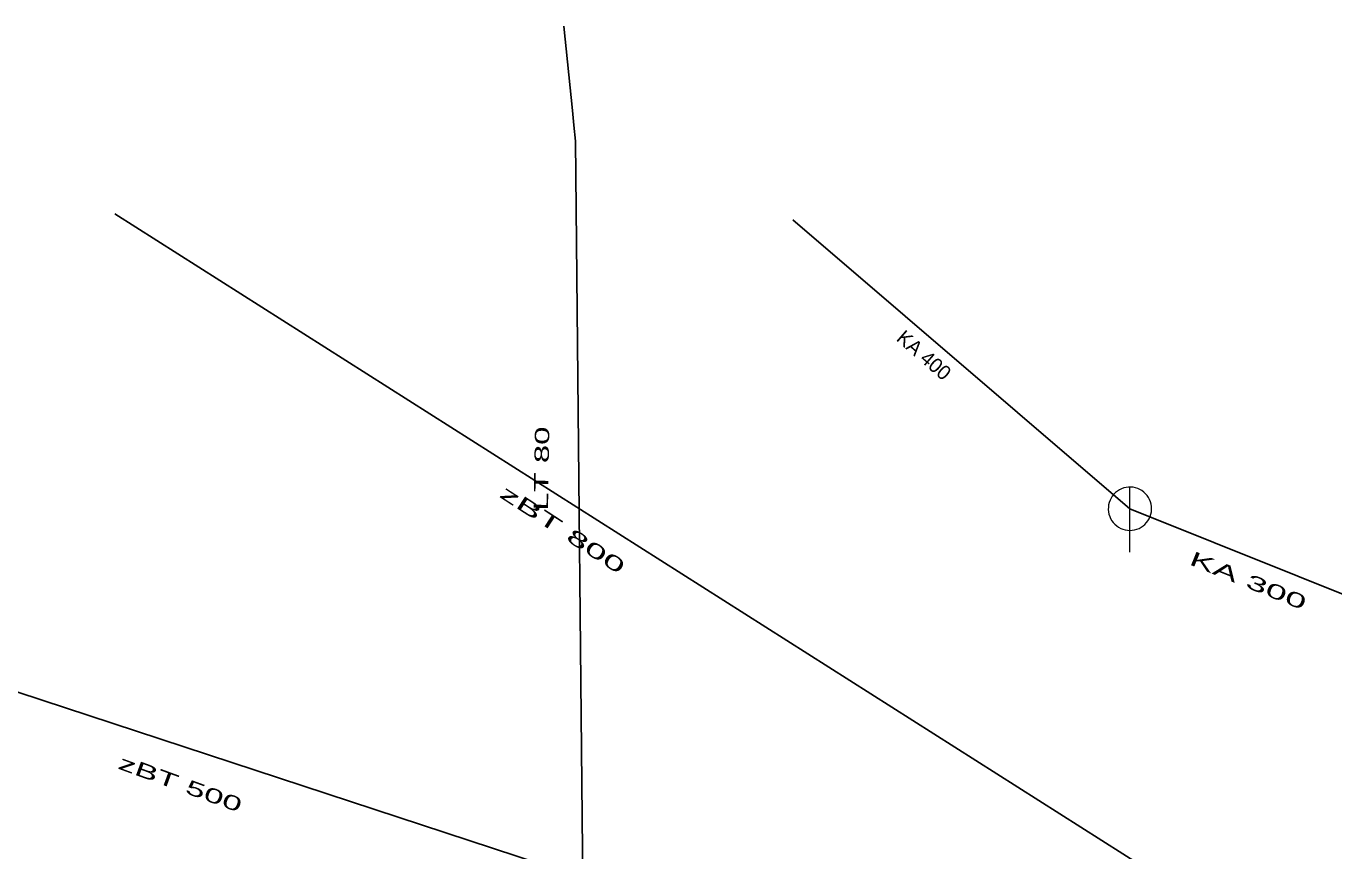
# Model space of a CAD drawing. Extents: x -688432 to -687974, y -973332 to -972704.
# Drawn here: x -688275.2 to -688214.9, y -972876 to -972837.9 of the extents above; entities that cross this region are included whole.
import ezdxf
from ezdxf.enums import TextEntityAlignment as Align

# ---------------------------------------------------------------- set-up
doc = ezdxf.new("R2010")
doc.units = 0
doc.header["$LTSCALE"] = 0.27
for name, color, linetype, lineweight in [('1', 7, 'Continuous', 25), ('14', 7, 'Continuous', 25), ('17', 7, 'Continuous', 25), ('22', 7, 'Continuous', 13)]:
    doc.layers.add(name, color=color, linetype=linetype, lineweight=lineweight)

msp = doc.modelspace()

# ---------------------------------------------------------------- linework, layer by layer
at = {"layer": '14'}
for p, q in [((-688221.777, -972877.88), (-688271.103, -972846.579)), ((-688224.272, -972860.177), (-688239.823, -972846.848))]:
    msp.add_line(p, q, dxfattribs=at)
for points in [[(-688207.188, -972867.028), (-688212.648, -972864.838), (-688224.272, -972860.177)], [(-688217.084, -972889.702), (-688227.642, -972884.745), (-688247.084, -972877.999), (-688290.938, -972863.596)]]:
    msp.add_lwpolyline(points, dxfattribs=at)
at = {"layer": '17'}
msp.add_lwpolyline([(-688249.47, -972882.184), (-688249.846, -972843.218), (-688249.92, -972842.489), (-688249.989, -972841.809), (-688250.385, -972837.918)], dxfattribs=at)
at = {"layer": '22'}
msp.add_line((-688224.272, -972862.177), (-688224.271, -972859.177), dxfattribs=at)
msp.add_lwpolyline([(-688223.272, -972860.177), (-688223.277, -972860.068), (-688223.295, -972859.96), (-688223.325, -972859.854), (-688223.365, -972859.753), (-688223.417, -972859.656), (-688223.479, -972859.566), (-688223.551, -972859.483), (-688223.631, -972859.409), (-688223.719, -972859.343), (-688223.813, -972859.288), (-688223.913, -972859.243), (-688224.018, -972859.21), (-688224.125, -972859.188), (-688224.234, -972859.178), (-688224.344, -972859.18), (-688224.452, -972859.194), (-688224.559, -972859.219), (-688224.662, -972859.256), (-688224.76, -972859.305), (-688224.852, -972859.363), (-688224.938, -972859.432), (-688225.015, -972859.509), (-688225.084, -972859.595), (-688225.143, -972859.687), (-688225.191, -972859.785), (-688225.228, -972859.888), (-688225.254, -972859.995), (-688225.268, -972860.103), (-688225.271, -972860.213), (-688225.261, -972860.322), (-688225.24, -972860.429), (-688225.206, -972860.533), (-688225.162, -972860.633), (-688225.107, -972860.728), (-688225.041, -972860.816), (-688224.967, -972860.896), (-688224.884, -972860.968), (-688224.794, -972861.03), (-688224.698, -972861.082), (-688224.596, -972861.123), (-688224.491, -972861.153), (-688224.383, -972861.171), (-688224.273, -972861.177), (-688224.164, -972861.171), (-688224.056, -972861.153), (-688223.951, -972861.124), (-688223.849, -972861.083), (-688223.752, -972861.031), (-688223.662, -972860.969), (-688223.579, -972860.898), (-688223.504, -972860.818), (-688223.439, -972860.73), (-688223.383, -972860.636), (-688223.339, -972860.536), (-688223.305, -972860.432), (-688223.283, -972860.324), (-688223.273, -972860.215)], close=True, dxfattribs=at)

# ---------------------------------------------------------------- texts
at = {"layer": '1'}
msp.add_text('KA 400', height=0.6667, rotation=319, dxfattribs=at).set_placement((-688233.9901, -972853.3445), align=Align.CENTER)
msp.add_text('KA 400', height=0.6667, rotation=319, dxfattribs=at).set_placement((-688233.9901, -972853.3445), align=Align.CENTER)
msp.add_text('KA 400', height=0.6667, rotation=319, dxfattribs=at).set_placement((-688233.9901, -972853.3445), align=Align.CENTER)
msp.add_text('KA 400', height=0.6667, rotation=319, dxfattribs=at).set_placement((-688233.9901, -972853.3445), align=Align.CENTER)
msp.add_text('KA 400', height=0.6667, rotation=319, dxfattribs=at).set_placement((-688233.9901, -972853.3445), align=Align.CENTER)
for s, rotation, width, p in [('LT 80 ', 89, 1.7, (-688251.0809, -972858.1198)), ('LT 80 ', 89, 1.7, (-688251.0809, -972858.1198)), ('LT 80 ', 89, 1.7, (-688251.0809, -972858.1198)), ('LT 80 ', 89, 1.7, (-688251.0809, -972858.1198)), ('LT 80 ', 89, 1.7, (-688251.0809, -972858.1198)), ('zBT 800 ', 327, 2, (-688250.4165, -972861.5496)), ('zBT 800 ', 327, 2, (-688250.4165, -972861.5496)), ('zBT 800 ', 327, 2, (-688250.4165, -972861.5496)), ('zBT 800 ', 327, 2, (-688250.4165, -972861.5496)), ('zBT 800 ', 327, 2, (-688250.4165, -972861.5496)), ('KA 300', 338, 1.95, (-688218.9409, -972863.7974)), ('KA 300', 338, 1.95, (-688218.9409, -972863.7974)), ('KA 300', 338, 1.95, (-688218.9409, -972863.7974)), ('KA 300', 338, 1.95, (-688218.9409, -972863.7974)), ('KA 300', 338, 1.95, (-688218.9409, -972863.7974)), ('zBT 500 ', 340, 1.8, (-688267.982, -972873.2478)), ('zBT 500 ', 340, 1.8, (-688267.982, -972873.2478)), ('zBT 500 ', 340, 1.8, (-688267.982, -972873.2478)), ('zBT 500 ', 340, 1.8, (-688267.982, -972873.2478)), ('zBT 500 ', 340, 1.8, (-688267.982, -972873.2478))]:
    msp.add_text(s, height=0.6667, rotation=rotation, dxfattribs=dict(at, width=width)).set_placement(p, align=Align.CENTER)

doc.saveas('drawing.dxf')
